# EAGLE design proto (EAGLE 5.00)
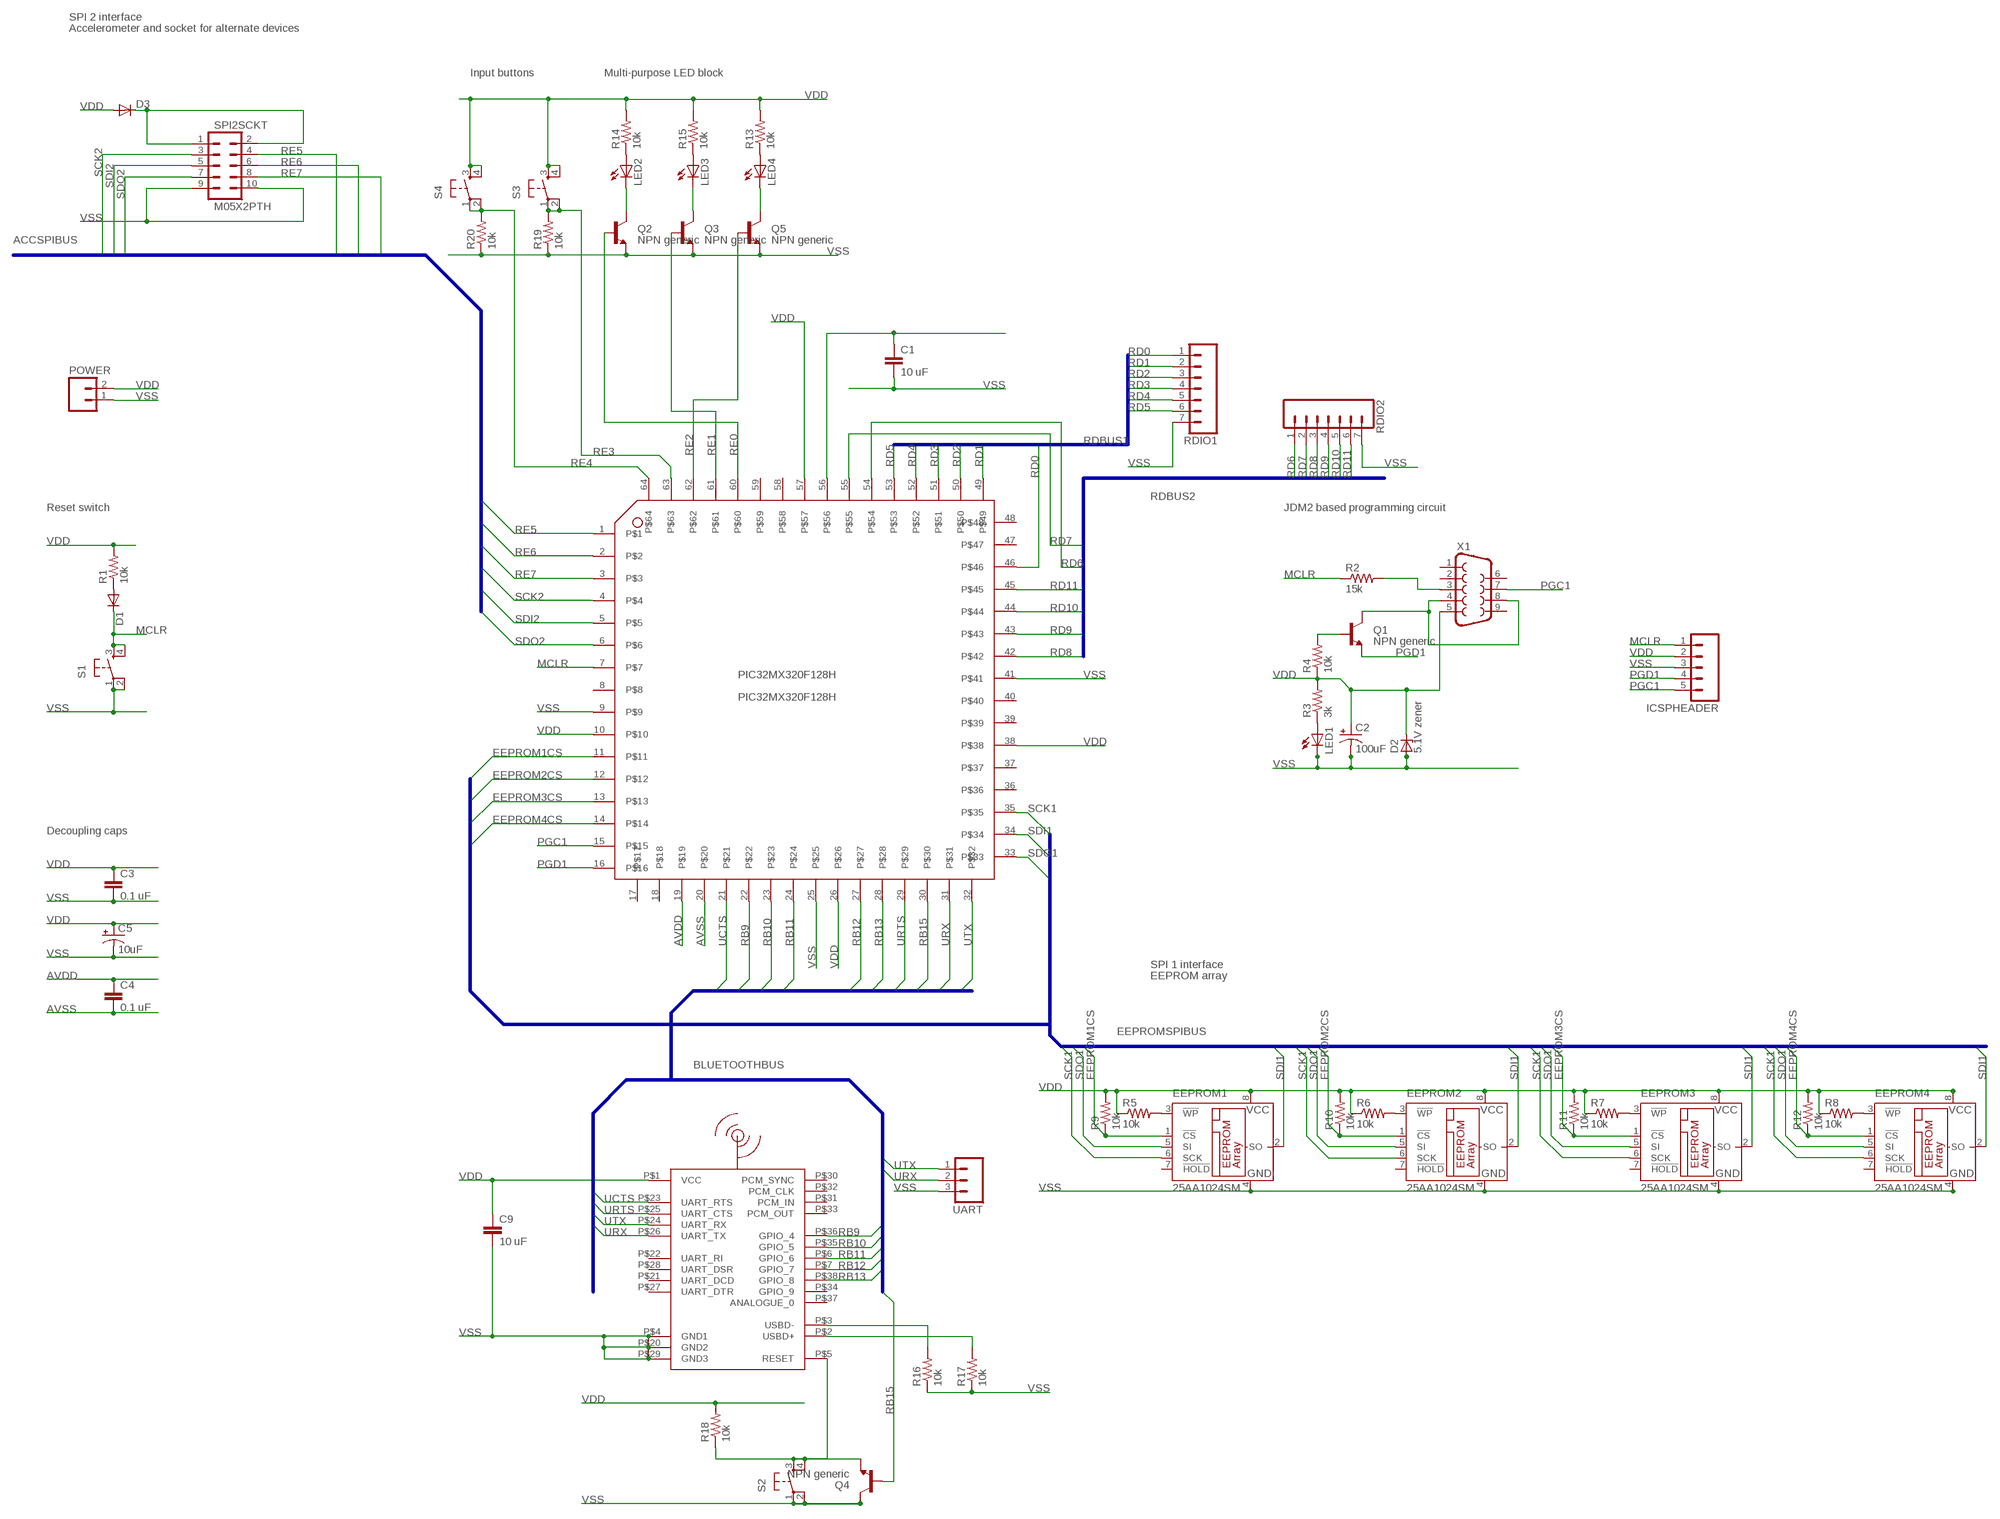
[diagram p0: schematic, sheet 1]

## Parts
C1  10 uF  CAP0603  [0603]
C2  100uF  CAP_POLPTH1  [CPOL-RADIAL-100UF-25V]
C3  0.1 uF  CAP0603  [0603]
C4  0.1 uF  CAP0603  [0603]
C5  10uF  CAP_POLPTH1  [CPOL-RADIAL-100UF-25V]
C9  10 uF  CAP0603  [0603]
D1  DIODESMA  [SMA-DIODE]
D2  5.1V zener  ZENER-DIODESMB  [SMB]
D3  DIODESMA  [SMA-DIODE]
EEPROM1  25AA1024SM  [SO-08M]
EEPROM2  25AA1024SM  [SO-08M]
EEPROM3  25AA1024SM  [SO-08M]
EEPROM4  25AA1024SM  [SO-08M]
ICSPHEADER  M05  [1X05]
LED1  LED1206  [LED-1206]
LED2  LED1206  [LED-1206]
LED3  LED1206  [LED-1206]
LED4  LED1206  [LED-1206]
PIC32MX320F128H  PIC32MX320F128H  [TQFP64]
POWER  M02PTH  [1X02]
Q1  NPN generic  TRANSISTOR_NPNSOT23  [SOT23]
Q2  NPN generic  TRANSISTOR_NPNSOT23  [SOT23]
Q3  NPN generic  TRANSISTOR_NPNSOT23  [SOT23]
Q4  NPN generic  TRANSISTOR_NPNSOT23  [SOT23]
Q5  NPN generic  TRANSISTOR_NPNSOT23  [SOT23]
R1  10k  RESISTOR0603  [0603]
R2  15k  RESISTOR0603  [0603]
R3  3k  RESISTOR0603  [0603]
R4  10k  RESISTOR0603  [0603]
R5  10k  RESISTOR0603  [0603]
R6  10k  RESISTOR0603  [0603]
R7  10k  RESISTOR0603  [0603]
R8  10k  RESISTOR0603  [0603]
R9  10k  RESISTOR0603  [0603]
R10  10k  RESISTOR0603  [0603]
R11  10k  RESISTOR0603  [0603]
R12  10k  RESISTOR0603  [0603]
R13  10k  RESISTOR0603  [0603]
R14  10k  RESISTOR0603  [0603]
R15  10k  RESISTOR0603  [0603]
R16  10k  RESISTOR0603  [0603]
R17  10k  RESISTOR0603  [0603]
R18  10k  RESISTOR0603  [0603]
R19  10k  RESISTOR0603  [0603]
R20  10k  RESISTOR0603  [0603]
RDIO1  M07  [1X07]
RDIO2  M07  [1X07]
S1  TAC_SWITCHSND  [TACTILE_SWITCH_SMD]
S2  TAC_SWITCHSND  [TACTILE_SWITCH_SMD]
S3  TAC_SWITCHSND  [TACTILE_SWITCH_SMD]
S4  TAC_SWITCHSND  [TACTILE_SWITCH_SMD]
SPI2SCKT  M05X2PTH  [AVR_ICSP]
U$2  BISMS02BI-01  [BISM]
UART  M03PTH  [1X03]
X1  DB9  [DB9]

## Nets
AVDD: C4.1 PIC32MX320F128H.19
AVSS: C4.2 PIC32MX320F128H.20
EEPROM1CS: EEPROM1.1(!CS) PIC32MX320F128H.11 R9.1
EEPROM2CS: EEPROM2.1(!CS) PIC32MX320F128H.12 R10.1
EEPROM3CS: EEPROM3.1(!CS) PIC32MX320F128H.13 R11.1
EEPROM4CS: EEPROM4.1(!CS) PIC32MX320F128H.14 R12.1
MCLR: D1.C ICSPHEADER.1 PIC32MX320F128H.7 R2.1 S1.3 S1.4
N$1: C1.1 PIC32MX320F128H.56
N$2: D1.A R1.1
N$3: R2.2 X1.3
N$4: Q1.3(C) X1.4 X1.8
N$5: LED1.A R3.1
N$6: Q1.1(B) R4.2
N$7: EEPROM4.3(!WP) R8.2
N$8: EEPROM3.3(!WP) R7.2
N$9: EEPROM2.3(!WP) R6.2
N$10: EEPROM1.3(!WP) R5.2
N$11: R16.2 U$2.P$3(USBD-)
N$12: LED4.A R13.1
N$13: LED4.C Q5.3(C)
N$15: D3.C SPI2SCKT.1 SPI2SCKT.2
N$16: LED2.A R14.1
N$17: LED3.A R15.1
N$18: LED2.C Q2.3(C)
N$19: LED3.C Q3.3(C)
N$20: R17.2 U$2.P$2(USBD+)
N$21: Q4.2(E) R18.1 S2.3 S2.4 U$2.P$5(RESET)
PGC1: ICSPHEADER.5 PIC32MX320F128H.15 X1.7
PGD1: ICSPHEADER.4 PIC32MX320F128H.16 Q1.2(E)
RB9: PIC32MX320F128H.22 U$2.P$36(GPIO_4)
RB10: PIC32MX320F128H.23 U$2.P$35(GPIO_5)
RB11: PIC32MX320F128H.24 U$2.P$6(GPIO_6)
RB12: PIC32MX320F128H.27 U$2.P$7(GPIO_7)
RB13: PIC32MX320F128H.28 U$2.P$38(GPIO_8)
RB15: PIC32MX320F128H.30 Q4.1(B)
RD0: PIC32MX320F128H.46 RDIO1.1
RD1: PIC32MX320F128H.49 RDIO1.2
RD2: PIC32MX320F128H.50 RDIO1.3
RD3: PIC32MX320F128H.51 RDIO1.4
RD4: PIC32MX320F128H.52 RDIO1.5
RD5: PIC32MX320F128H.53 RDIO1.6
RD6: PIC32MX320F128H.54 RDIO2.1
RD7: PIC32MX320F128H.55 RDIO2.2
RD8: PIC32MX320F128H.42 RDIO2.3
RD9: PIC32MX320F128H.43 RDIO2.4
RD10: PIC32MX320F128H.44 RDIO2.5
RD11: PIC32MX320F128H.45 RDIO2.6
RE0: PIC32MX320F128H.60 Q2.1(B)
RE1: PIC32MX320F128H.61 Q3.1(B)
RE2: PIC32MX320F128H.62 Q5.1(B)
RE3: PIC32MX320F128H.63 R19.2 S3.1 S3.2
RE4: PIC32MX320F128H.64 R20.2 S4.1 S4.2
RE5: PIC32MX320F128H.1 SPI2SCKT.4
RE6: PIC32MX320F128H.2 SPI2SCKT.6
RE7: PIC32MX320F128H.3 SPI2SCKT.8
SCK1: EEPROM1.6(SCK) EEPROM2.6(SCK) EEPROM3.6(SCK) EEPROM4.6(SCK) PIC32MX320F128H.35
SCK2: PIC32MX320F128H.4 SPI2SCKT.3
SDI1: EEPROM1.2(SO) EEPROM2.2(SO) EEPROM3.2(SO) EEPROM4.2(SO) PIC32MX320F128H.34
SDI2: PIC32MX320F128H.5 SPI2SCKT.5
SDO1: EEPROM1.5(SI) EEPROM2.5(SI) EEPROM3.5(SI) EEPROM4.5(SI) PIC32MX320F128H.33
SDO2: PIC32MX320F128H.6 SPI2SCKT.7
UCTS: PIC32MX320F128H.21 U$2.P$23(UART_RTS)
URTS: PIC32MX320F128H.29 U$2.P$25(UART_CTS)
URX: PIC32MX320F128H.31 U$2.P$26(UART_TX) UART.2
UTX: PIC32MX320F128H.32 U$2.P$24(UART_RX) UART.1
VDD: C2.1(+) C3.1 C5.1(+) C9.1 D2.C D3.A EEPROM1.8(VCC) EEPROM2.8(VCC) EEPROM3.8(VCC) EEPROM4.8(VCC) ICSPHEADER.2 PIC32MX320F128H.10 PIC32MX320F128H.26 PIC32MX320F128H.38 PIC32MX320F128H.57 POWER.2 R1.2 R3.2 R4.1 R5.1 R6.1 R7.1 R8.1 R9.2 R10.2 R11.2 R12.2 R13.2 R14.2 R15.2 R18.2 S3.3 S3.4 S4.3 S4.4 U$2.P$1(VCC) X1.5
VSS: C1.2 C2.2(-) C3.2 C5.2(-) C9.2 D2.A EEPROM1.4(GND) EEPROM2.4(GND) EEPROM3.4(GND) EEPROM4.4(GND) ICSPHEADER.3 LED1.C PIC32MX320F128H.9 PIC32MX320F128H.25 PIC32MX320F128H.41 POWER.1 Q2.2(E) Q3.2(E) Q4.3(C) Q5.2(E) R16.1 R17.1 R19.1 R20.1 RDIO1.7 RDIO2.7 S1.1 S1.2 S2.1 S2.2 SPI2SCKT.9 SPI2SCKT.10 U$2.P$4(GND1) U$2.P$20(GND2) U$2.P$29(GND3) UART.3
Unconnected: EEPROM1.7(!HOLD) EEPROM2.7(!HOLD) EEPROM3.7(!HOLD) EEPROM4.7(!HOLD) PIC32MX320F128H.8 PIC32MX320F128H.17 PIC32MX320F128H.18 PIC32MX320F128H.36 PIC32MX320F128H.37 PIC32MX320F128H.39 PIC32MX320F128H.40 PIC32MX320F128H.47 PIC32MX320F128H.48 PIC32MX320F128H.58 PIC32MX320F128H.59 U$2.P$21(UART_DCD) U$2.P$22(UART_RI) U$2.P$27(UART_DTR) U$2.P$28(UART_DSR) U$2.P$30(PCM_SYNC) U$2.P$31(PCM_IN) U$2.P$32(PCM_CLK) U$2.P$33(PCM_OUT) U$2.P$34(GPIO_9) U$2.P$37(ANALOGUE_0) X1.1 X1.2 X1.6 X1.9

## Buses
EEPROMSPIBUS
ACCSPIBUS
RDBUS1
RDBUS2
BLUETOOTHBUS

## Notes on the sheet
- SPI 2 interface
- Accelerometer and socket for alternate devices
- Input buttons | Multi-purpose LED block
- Reset switch | JDM2 based programming circuit
- Decoupling caps
- SPI 1 interface
- EEPROM array

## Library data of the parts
C1 C3 C4 C9 = SparkFun:CAP: Capacitor
C2 C5 = SparkFun:CAP_POL: Capacitor Polarized
D1 D3 = SparkFun:DIODE: Diode
D2 = diode:ZENER-DIODE: Z-Diode
EEPROM1-EEPROM4 = microchip:25*: Serial EEPROM SPI bus
ICSPHEADER = SparkFun:M05: Header 5 Standard 5-pin 0.1" header. Use with straight break away headers (SKU : PRT-00116), right angle break away headers (PRT-00553), swiss pins (PRT-00743), machine pins (PRT-00117), and female headers (PRT-00115). Molex polarized connector foot print use with SKU : PRT-08230 with associated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
LED1-LED4 = SparkFun:LED: LEDs
PIC32MX320F128H = microchip:PIC32MX320F128H: 64 pin general purpose 32bit PIC microcontroller Source: http://ww1.microchip.com/downloads/en/DeviceDoc/PIC32MX_Datasheet_v3_61143C.pdf
POWER = SparkFun:M02: Header 2
Q1-Q5 = SparkFun:TRANSISTOR_NPN: Transistor NPN BJT configuration in SOT23 package. MMBT2222 is the common NPN we use. Double check BCE configuration again layout.
R1-R20 = SparkFun:RESISTOR: Resistor
RDIO1 RDIO2 = SparkFun:M07: Header 7 Standard 7-pin 0.1" header. Use with straight break away headers (SKU : PRT-00116), right angle break away headers (PRT-00553), swiss pins (PRT-00743), machine pins (PRT-00117), and female headers (PRT-00115).
S1-S4 = SparkFun:TAC_SWITCH: Momentary Switch Button commonly used for reset or general input. Spark Fun Electronics SKU : COM-00097
SPI2SCKT = SparkFun:M05X2: Header 5x2 Standard 10-pin dual row 0.1" header. Commonly used with AVR-ISP. Use with Spark Fun Electronics SKU: PRT-00778
U$2 = errata:BISMS02BI-01: Ezurio BISM bluetooth module http://uk.rs-online.com/web/search/searchBrowseAction.html?method=getProduct&R=0188949 The Ezurio Embedded Bluetooth Module provides a robust and reliable Bluetooth connection along with a simple AT command based programming interface. The BISMII module is a Class 1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
UART = SparkFun:M03: Header 3 Standard 3-pin 0.1" header. Use with straight break away headers (SKU : PRT-00116), right angle break away headers (PRT-00553), swiss pins (PRT-00743), machine pins (PRT-00117), and female headers (PRT-00115). Molex polarized connector foot print use with SKU : PRT-08232 with associated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
X1 = SparkFun:DB9: DB9 Connector Standard DB9 (D-Sub 9) serial connector. Can be used for CAN bus as well as RS485 and RS232. Footprint production proven. Spark Fun Electronics SKU : PRT-00429

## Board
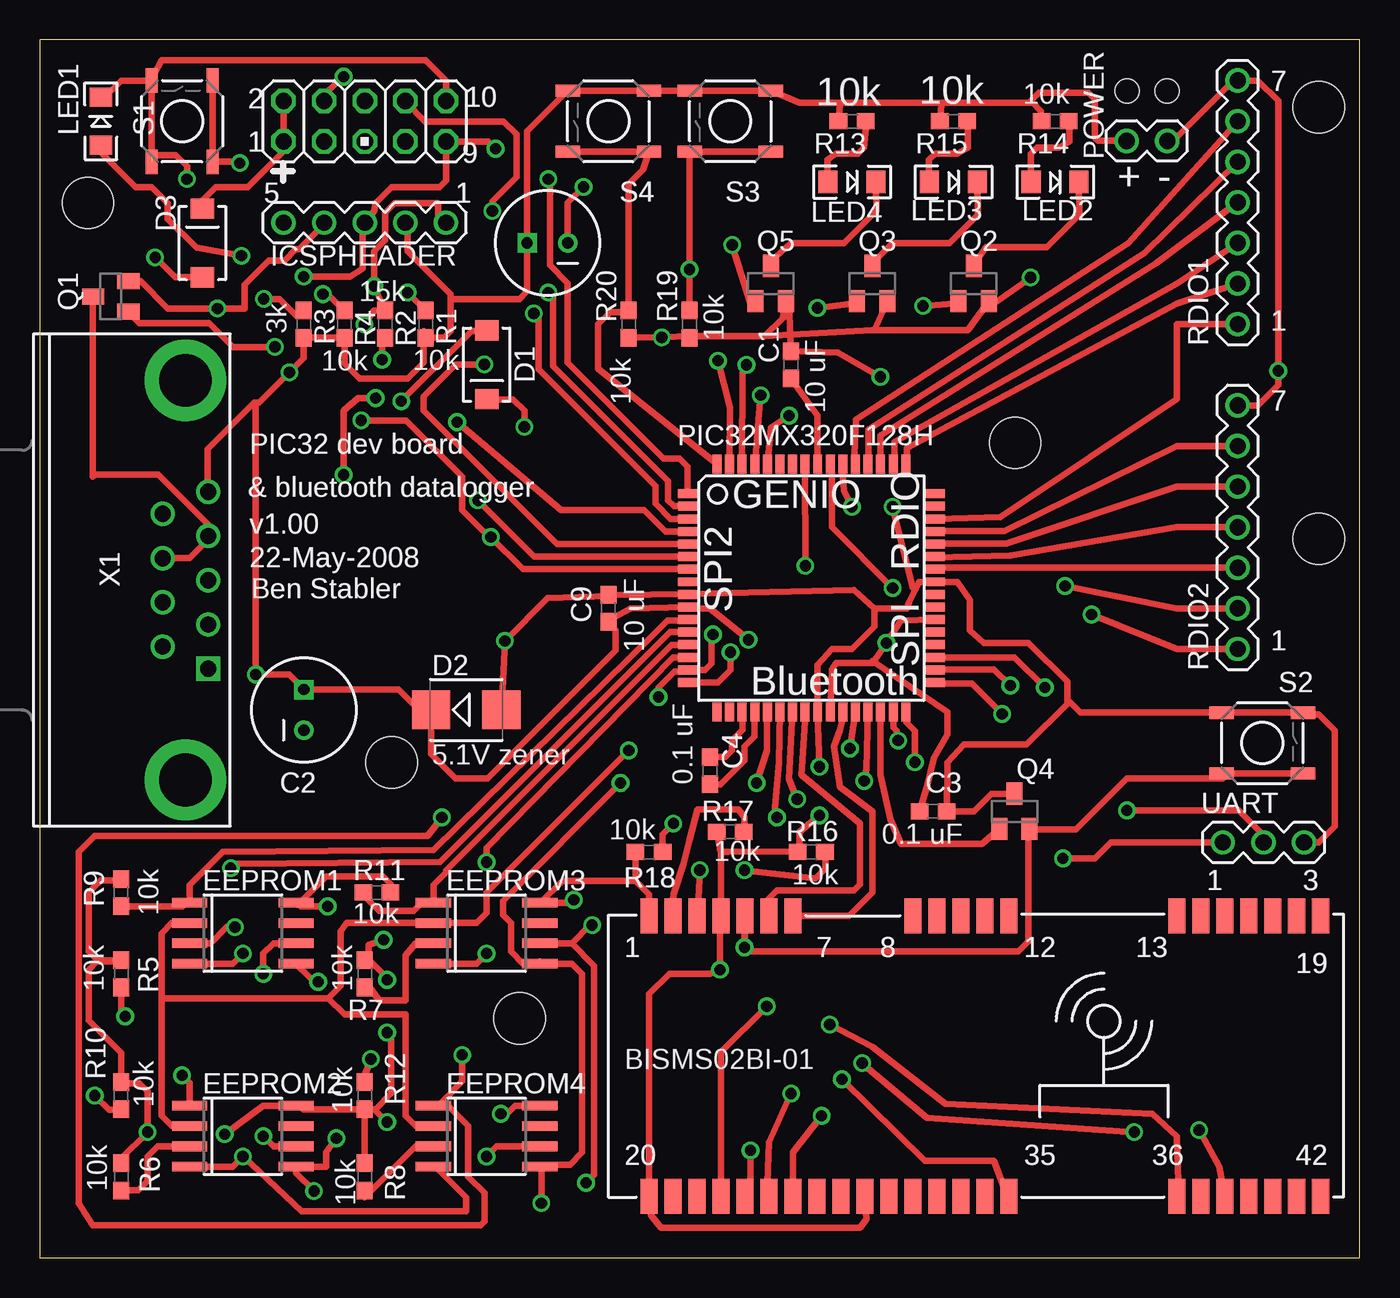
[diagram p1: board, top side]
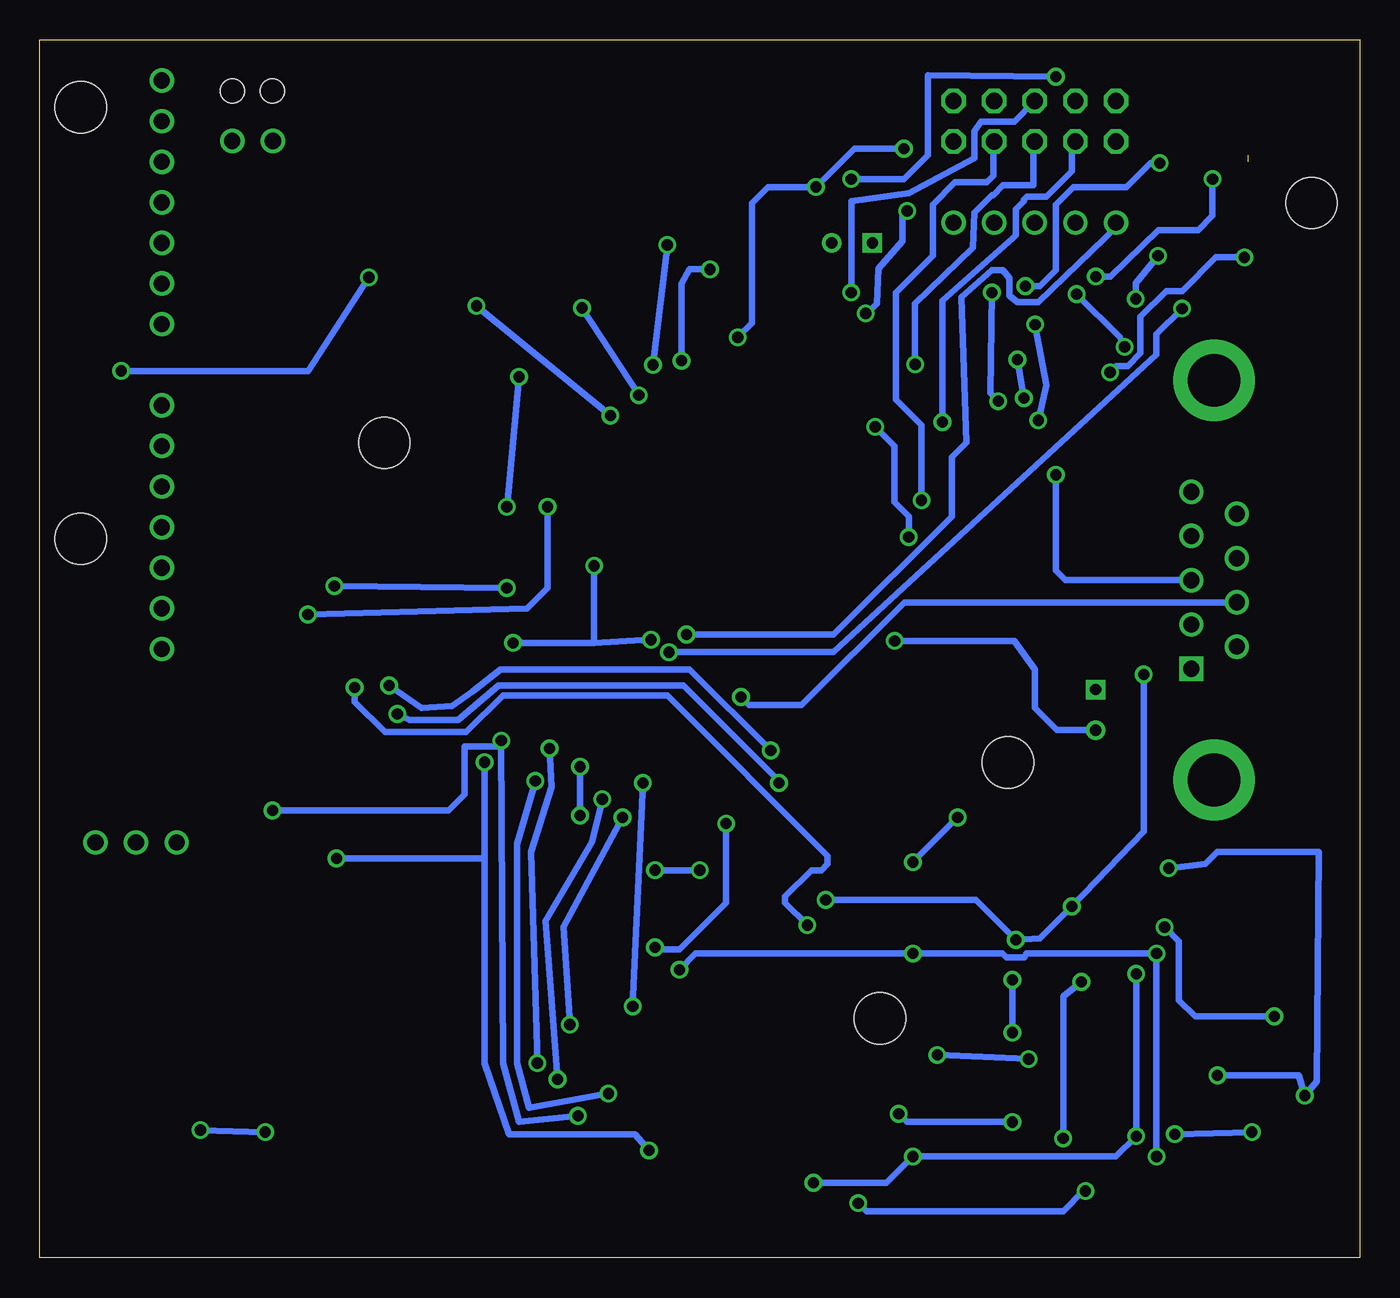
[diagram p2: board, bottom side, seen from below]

Size 82.55 x 76.2 mm. Coordinates in mm from the lower left corner, seen from the top.
Outline: 0,0 82.55,0 82.55,76.2 0,76.2 0,0
Copper layers (1*16): Top 0.035mm / dielectric 1.5mm / Bottom 0.035mm
Design rules "default": minimum track width 10mil, minimum drill 24mil, track to track 8mil, track to pad 8mil, pad to pad 8mil, via to via 8mil, smd to smd 8mil, copper to edge 40mil, drill to drill 8mil, minimum pad ring 10mil, minimum via ring 8mil, stop-mask expansion 4mil, vias tented up to drill 0mil, thermal gap 10mil
Holes 1.5 mm at 68,73 70.5,73
Holes 3.2 mm at 3,66 80,72 80,45 30,15 22,31 61,51

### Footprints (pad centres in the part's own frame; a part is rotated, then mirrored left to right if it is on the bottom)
0603 = smd 1.1 x 1: 1 -0.85,0; 2 0.85,0
CPOL-RADIAL-100UF-25V = drill 0.7 square: 1 1.27,0 | drill 0.7 round: 2 -1.27,0
SMA-DIODE = smd 1.27 x 1.47: A -2.15,0; C 2.15,0
SMB = smd 2.4 x 2.4: A 2.2,0; C -2.2,0
SO-08M = smd 0.6 x 2.2: 1 -1.905,-3.33; 2 -0.635,-3.33; 3 0.635,-3.33; 4 1.905,-3.33; 5 1.905,3.33; 6 0.635,3.33; 7 -0.635,3.33; 8 -1.905,3.33
1X05 = drill 1.016 round: 1 0,0; 2 2.54,0; 3 5.08,0; 4 7.62,0; 5 10.16,0
LED-1206 = smd 1.2 x 1.4: A -1.5,0; C 1.5,0
TQFP64 = smd 1.194 x 0.559: 1 -7.76,5.905; 2 -7.76,5.118; 3 -7.76,4.331; 4 -7.76,3.543; 5 -7.76,2.756; 6 -7.76,1.968; 7 -7.76,1.181; 8 -7.76,0.394; 9 -7.76,-0.394; 10 -7.76,-1.181; 11 -7.76,-1.968; 12 -7.76,-2.756; 13 -7.76,-3.543; 14 -7.76,-4.331; 15 -7.76,-5.118; 16 -7.76,-5.905; 33 7.76,-5.905; 34 7.76,-5.118; 35 7.76,-4.331; 36 7.76,-3.543; 37 7.76,-2.756; 38 7.76,-1.968; 39 7.76,-1.181; 40 7.76,-0.394; 41 7.76,0.394; 42 7.76,1.181; 43 7.76,1.968; 44 7.76,2.756; 45 7.76,3.543; 46 7.76,4.331; 47 7.76,5.118; 48 7.76,5.905 | smd 0.559 x 1.194: 17 -5.905,-7.76; 18 -5.118,-7.76; 19 -4.331,-7.76; 20 -3.543,-7.76; 21 -2.756,-7.76; 22 -1.968,-7.76; 23 -1.181,-7.76; 24 -0.394,-7.76; 25 0.394,-7.76; 26 1.181,-7.76; 27 1.968,-7.76; 28 2.756,-7.76; 29 3.543,-7.76; 30 4.331,-7.76; 31 5.118,-7.76; 32 5.905,-7.76; 49 5.905,7.76; 50 5.118,7.76; 51 4.331,7.76; 52 3.543,7.76; 53 2.756,7.76; 54 1.968,7.76; 55 1.181,7.76; 56 0.394,7.76; 57 -0.394,7.76; 58 -1.181,7.76; 59 -1.968,7.76; 60 -2.756,7.76; 61 -3.543,7.76; 62 -4.331,7.76; 63 -5.118,7.76; 64 -5.905,7.76
1X02 = drill 1.016 round: 1 0,0; 2 2.54,0
SOT23 = smd 1 x 1.4: 1 -0.95,-1.1; 2 0.95,-1.1; 3 0,1.1
1X07 = drill 1.016 round: 1 0,0; 2 2.54,0; 3 5.08,0; 4 7.62,0; 5 10.16,0; 6 12.7,0; 7 15.24,0
TACTILE_SWITCH_SMD = smd 1.524 x 0.762: 1 -2.54,1.905; 2 2.54,1.905; 3 -2.54,-1.905; 4 2.54,-1.905
AVR_ICSP = drill 1.016 octagon: 1 -1.27,5.08; 2 1.27,5.08; 3 -1.27,2.54; 4 1.27,2.54; 5 -1.27,0; 6 1.27,0; 7 -1.27,-2.54; 8 1.27,-2.54; 9 -1.27,-5.08; 10 1.27,-5.08
BISM = smd 1.067 x 2.184: P$1 2.55,17.6; P$2 4.05,17.6; P$3 5.55,17.6; P$4 7.05,17.6; P$5 8.55,17.6; P$6 10.05,17.6; P$7 11.55,17.6; P$8 19.05,17.6; P$9 20.55,17.6; P$10 22.05,17.6; P$11 23.55,17.6; P$12 25.05,17.6; P$13 35.55,17.6; P$14 37.05,17.6; P$15 38.55,17.6; P$16 40.05,17.6; P$17 41.55,17.6; P$18 43.05,17.6; P$19 44.55,17.6; P$20 2.55,0.05; P$21 4.05,0.05; P$22 5.55,0.05; P$23 7.05,0.05; P$24 8.55,0.05; P$25 10.05,0.05; P$26 11.55,0.05; P$27 13.05,0.05; P$28 14.55,0.05; P$29 16.05,0.05; P$30 17.55,0.05; P$31 19.05,0.05; P$32 20.55,0.05; P$33 22.05,0.05; P$34 23.55,0.05; P$35 25.05,0.05; P$36 35.55,0.05; P$37 37.05,0.05; P$38 38.55,0.05; P$39 40.05,0.05; P$40 41.55,0.05; P$41 43.05,0.05; P$42 44.55,0.05
1X03 = drill 1.016 round: 1 0,0; 2 2.54,0; 3 5.08,0
DB9 = drill 1.016 square: 1 -5.54,-1.42 | drill 1.016 round: 2 -2.77,-1.42; 3 0,-1.42; 4 2.77,-1.42; 5 5.54,-1.42; 6 -4.15,1.42; 7 -1.38,1.42; 8 1.38,1.42; 9 4.15,1.42 | drill 3.302 pad 5.08 round: G1 -12.5,0; G2 12.5,0

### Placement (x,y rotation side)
C1  46.99,55.88 90 top
C2  16.51,34.29 90 top
C3  55.88,27.94 0 top
C4  41.91,30.48 270 top
C5  31.75,63.5 180 top
C9  35.56,40.64 90 top
D1  27.94,55.88 270 top
D2  26.67,34.29 0 top
D3  10.16,63.5 90 top
EEPROM1  12.7,20.32 270 top
EEPROM2  12.7,7.62 270 top
EEPROM3  27.94,20.32 270 top
EEPROM4  27.94,7.62 270 top
ICSPHEADER  25.4,64.77 180 top
LED1  3.81,71.12 90 top
LED2  63.5,67.31 0 top
LED3  57.15,67.31 0 top
LED4  50.8,67.31 0 top
PIC32MX320F128H  48.26,41.91 0 top
POWER  70.52,69.89 180 top
Q1  4.43,60.15 90 top
Q2  58.42,60.96 0 top
Q3  52.07,60.96 0 top
Q4  60.96,27.94 0 top
Q5  45.72,60.96 0 top
R1  24.13,58.42 270 top
R2  21.59,58.42 270 top
R3  16.51,58.42 270 top
R4  19.05,58.42 90 top
R5  5.08,17.78 270 top
R6  5.08,5.08 270 top
R7  20.32,17.78 270 top
R8  20.32,5.08 270 top
R9  5.08,22.86 90 top
R10  5.08,10.16 90 top
R11  21.08,22.86 0 top
R12  20.32,10.16 270 top
R13  50.8,71.12 180 top
R14  63.5,71.12 180 top
R15  57.15,71.12 180 top
R16  48.26,25.4 0 top
R17  43.18,26.67 0 top
R18  38.1,25.4 180 top
R19  40.64,58.42 90 top
R20  36.83,58.42 90 top
RDIO1  74.93,58.42 90 top
RDIO2  74.93,38.1 90 top
S1  8.89,71.12 90 top
S2  76.47,32.21 0 top
S3  43.18,71.12 180 top
S4  35.56,71.12 180 top
SPI2SCKT  20.32,71.12 90 top
U$2  35.56,3.81 0 top
UART  74,26 0 top
X1  9.1,42.4 90 top

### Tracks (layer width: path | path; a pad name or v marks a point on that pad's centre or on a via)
AVDD
  Top 0.406: C4.1 42.89,31.33 43.31,31.75 43.31,32.38 43.94,33.02 43.94,34.16 PIC32MX320F128H.19
AVSS
  Top 0.406: C4.2 42.58,29.63 44.07,31.11 44.07,32 44.7,32.64 44.7,33.91 44.72,33.92 PIC32MX320F128H.20
EEPROM1CS
  Top 0.406: PIC32MX320F128H.11 40.5,39.89 40.51,39.88 39.24,39.88 38.35,38.99 24.64,25.53 11.43,25.4 9.37,23.34 EEPROM1.1 9.14,22.23 8.93,22.01 R9.1
EEPROM2CS  (via drill 0.7)
  Top 0.406: EEPROM2.1 9.37,10.95 v8.89,11.43 | v3.43,10.16 4.32,9.27 5.08,9.27 | 5.08,9.27 R10.1 | 5.08,9.27 5.21,9.14 | PIC32MX320F128H.12 39.41,39.15 25.02,24.77 12.19,24.64 v11.94,24.38
  Bottom 0.406: v8.89,11.43 3.81,11.43 v3.43,10.16 2.67,11.05 2.54,25.4 8.89,25.4 9.65,24.64 v11.94,24.38
EEPROM3CS
  Top 0.406: R11.1 20.23,22.77 20.19,22.73 21.21,21.72 23.37,21.72 23.88,22.23 EEPROM3.1 24.61,23.34 25.4,24.13 25.4,24.26 39.5,38.35 40.51,38.35 PIC32MX320F128H.13
EEPROM4CS  (via drill 0.7)
  Top 0.406: R12.1 20.32,11.43 v20.7,12.45 | EEPROM4.1 24.89,9.53 25.21,9.84 | v26.42,12.7 26.42,11.05 25.21,9.84 | PIC32MX320F128H.14 39.61,37.58 27.94,25.65 v27.94,24.77 | v25.15,27.56 24.26,26.42 3.43,26.42 2.41,25.4 2.41,3.43 3.3,2.03 27.56,2.03 27.81,2.29 27.81,4.06 26.8,5.08 26.8,8.26 25.21,9.84
  Bottom 0.406: v26.42,12.7 v20.7,12.45 | v25.15,27.56 v27.94,24.77
MCLR  (via drill 0.7)
  Top 0.406: 10.79,73.79 S1.4 S1.3 12.42,68.58 v12.5,68.5 | v20.89,60.8 R2.1 20.87,59.27 v20.3,58.4 | v20.89,60.8 20.9,63 21.59,63.69 21.59,65.39 22.2,66 24.9,66 24.9,65.3 25.4,64.8 ICSPHEADER.1 | v20.89,60.8 20.8,60.8 | v20.89,60.8 v20.9,60.8 | PIC32MX320F128H.7 30.21,43.09 v28.2,45.1 28.2,45 26.4,46.8 26.4,48.9 22.9,52.4 v20.1,52.4 | v30.3,52 30.3,53 29.6,53.7 27.9,53.7 27.87,53.73 | 27.87,53.73 27.8,53.8 | 27.87,53.73 D1.C
  Bottom 0.406: v12.5,68.5 13.1,68.5 14.6,67 17.9,67 19,65.9 19,61.8 20,60.8 v20.9,60.8 | v28.2,45.1 28.2,46.4 29.1,47.3 29.1,50.8 v30.3,52 | v20.3,58.4 19.6,54.6 v20.1,52.4
N$1
  Top 0.406: C1.1 48.64,52.7 48.64,49.4 PIC32MX320F128H.56
N$2  (via drill 0.7)
  Top 0.406: v23,60.4 R1.1 | v22.6,53.6 27,58 27.9,58 D1.A
  Bottom 0.406: v23,60.4 23.1,54.1 v22.6,53.6
N$3  (via drill 0.7)
  Top 0.406: v19,49 19,53 19.9,53.8 v21,53.8 | R2.2 21.63,57.57 21.7,57.5 21.4,57.2 v21.4,56.2
  Bottom 0.406: X1.3 18.4,42.4 19,43 v19,49 | v21,53.8 v21.4,56.2
N$4
  Top 0.406: X1.8 9.38,43.78 10.6,45 10.52,45.08 X1.4 10.52,45.88 7.4,49 3.4,49 3.3,48.9 3.3,60.1 3.35,60.15 | 3.35,60.15 3.4,60.2 | 3.35,60.15 Q1.3
N$5  (via drill 0.7)
  Top 0.406: LED1.A 3.81,69.19 6,67 7,67 8,66 8,65 9.8,63.2 v12.6,62.7 | v14,60 15,60 16,59 16.3,59 16.57,59.27 | 16.57,59.27 16.6,59.3 | 16.57,59.27 R3.1
  Bottom 0.406: v12.6,62.7 14,61 v14,60
N$6  (via drill 0.7)
  Top 0.406: 19.05,59.25 19.1,59.2 | 19.05,59.25 R4.2 | v17.7,60.3 18,60.3 19.05,59.25 | v14.7,57 12.1,57 10.6,58.5 6.2,58.5 5.53,59.17 Q1.1
  Bottom 0.406: v14.7,57 15,57.6 v17.7,60.3
N$7
  Top 0.406: EEPROM4.3 23.5,6.99 20.32,3.81 R8.2
N$8
  Top 0.406: EEPROM3.3 23.5,19.68 22.86,18.92 22.86,16.13 21.21,16.13 20.57,17.02 20.49,16.93 R7.2
N$9
  Top 0.406: R6.2 6.13,4.23 6.73,4.83 6.73,6.35 7.37,6.99 EEPROM2.3
N$10  (via drill 0.7)
  Top 0.406: R5.2 5.08,15.37 v5.33,15.11 | v12.19,20.7 11.68,20.7 10.67,19.68 EEPROM1.3 9.27,19.68
  Bottom 0.406: v5.33,15.11 10.29,15.11 11.3,16.13 11.3,19.81 v12.19,20.7
N$11  (via drill 0.7)
  Top 0.406: R16.2 49.15,24.38 48.51,23.75 v44.07,24.26 | U$2.P$3 41.15,21.34 v41.27,24.26
  Bottom 0.406: v41.27,24.26 v44.07,24.26
N$12
  Top 0.406: LED4.A 49.28,68.71 49.78,69.09 51.18,69.09 51.56,69.47 51.69,70.99 R13.1
N$13
  Top 0.406: LED4.C 52.32,65.53 50.29,63.5 46.99,63.5 45.72,62.36 Q5.3
N$15
  Top 0.406: SPI2SCKT.2 SPI2SCKT.1 15.24,69.24 13,67 11,67 10,66 10.16,65.84 D3.C
N$16
  Top 0.406: LED2.A 61.98,69.09 62.36,69.47 63.75,69.47 64.39,69.85 64.39,70.87 R14.1
N$17
  Top 0.406: LED3.A 55.63,68.71 56.01,69.09 57.4,69.09 58.04,69.47 58.04,71.12 R15.1
N$18
  Top 0.406: LED2.C 65.02,65.28 62.99,63.25 59.18,63.25 58.42,62.1 Q2.3
N$19
  Top 0.406: LED3.C 58.67,65.28 56.9,63.5 53.34,63.5 51.94,62.1 Q3.3
N$20
  Top 0.406: R17.2 44.07,27.56 43.69,28.07 41.15,28.07 40.64,26.16 40.26,24.64 39.62,22.73 39.5,21.46 U$2.P$2
N$21  (via drill 0.7)
  Top 0.406: 44.11,20.83 U$2.P$5 | 44.11,20.83 44.11,19.26 44.2,19.18 61.21,19.18 61.85,19.81 61.85,26.67 61.98,26.8 | 61.98,26.8 61.93,26.84 Q4.2 | R18.1 38.95,26.5 v39.62,27.18 | 44.11,20.83 44.07,20.83 v44.07,19.43 | S2.4 S2.3 73.93,30.07 74,30 68,30 64.8,26.8 61.98,26.8
  Bottom 0.406: v39.62,27.18 39.62,22.23 42.55,19.3 43.94,19.3 v44.07,19.43
PGC1  (via drill 0.7)
  Top 0.406: v42.1,39 42,38.9 42,37.2 41.59,36.79 PIC32MX320F128H.15 40.6,36.7 39.7,36.7 38.7,35.7 v38.7,35.1
  Bottom 0.406: v42.1,39 32.9,39 25.5,46.4 25.5,50.1 24.6,51 24.9,60.1 23,61.8 22.3,61.8 21.9,61.3 21.9,60.2 21.4,59.8 20.1,59.8 15.1,64.6 15.24,64.74 ICSPHEADER.5 | X1.7 28.48,41.02 34.9,34.6 38.2,34.6 v38.7,35.1
PGD1  (via drill 0.7)
  Top 0.406: PIC32MX320F128H.16 42.4,36.01 43.2,36.8 v43.2,37.9 | ICSPHEADER.4 17.78,64.72 17.8,64.7 16.2,63.1 16,63.1 15.3,62.4 14.3,62.4 12.8,60.9 12.8,59.4 v11.1,59.4 8,59.4 6.3,61.1 Q1.2
  Bottom 0.406: v43.2,37.9 32.9,37.9 12.7,56.5 12.7,57.8 v11.1,59.4
RB9  (via drill 0.7)
  Top 0.406: PIC32MX320F128H.22 46.23,30.99 45.97,28.19 v46.1,27.56 | v49.4,14.61 52.07,13.21 56.64,9.65 69.6,9.02 71.12,7.62 71.25,3.81 U$2.P$36
  Bottom 0.406: v46.1,27.56 49.78,20.7 v49.4,14.61
RB10  (via drill 0.7)
  Top 0.406: PIC32MX320F128H.23 46.86,29.97 v47.37,28.7 | v50.16,11.18 55.37,6.1 59.69,6.1 60.58,3.68 U$2.P$35
  Bottom 0.406: v47.37,28.7 48.01,26.04 50.93,21.08 v50.16,11.18
RB11
  Top 0.406: U$2.P$6 45.61,22.5 46.1,22.99 50.93,22.99 51.31,23.37 51.31,27.18 47.62,30.23 47.88,34.04 PIC32MX320F128H.24
RB12
  Top 0.406: U$2.P$7 50.62,21.41 52.07,22.86 52.07,27.94 50.04,29.46 49.66,32 50.04,33.02 50.29,34.04 50.18,34.15 | 50.18,34.15 50.16,34.16 | 50.18,34.15 PIC32MX320F128H.27
RB13  (via drill 0.7)
  Top 0.406: v50.67,31.88 PIC32MX320F128H.28 | v51.44,12.19 55.5,8.76 v68.45,7.87 | v72.52,8 73.79,5.71 74.17,3.68 U$2.P$38
  Bottom 0.406: v50.67,31.88 50.55,29.46 51.82,25.4 v51.44,12.19 | v68.45,7.87 v72.52,8
RB15
  Top 0.406: Q4.1 58.93,25.91 53.85,25.91 53.21,27.43 52.58,30.23 52.58,33.91 PIC32MX320F128H.30
RD0
  Top 0.406: PIC32MX320F128H.46 60.07,46.35 71.12,53.72 71.12,58.42 RDIO1.1
RD1
  Top 0.406: RDIO1.2 71.12,59.69 54.23,50.67 54.23,49.53 PIC32MX320F128H.49
RD2
  Top 0.406: RDIO1.3 71.12,60.96 53.47,51.05 53.47,49.91 PIC32MX320F128H.50
RD3
  Top 0.406: RDIO1.4 69.85,62.23 52.58,51.44 52.58,49.66 PIC32MX320F128H.51
RD4
  Top 0.406: RDIO1.5 69.09,62.87 51.82,51.82 51.82,49.53 PIC32MX320F128H.52
RD5
  Top 0.406: RDIO1.6 68.07,63.5 51.05,52.45 50.93,49.53 PIC32MX320F128H.53
RD6  (via drill 0.7)
  Top 0.406: RDIO2.1 71.12,38.1 v65.79,40.26 | v50.8,46.99 50.29,48.01 50.16,49.53 PIC32MX320F128H.54
  Bottom 0.406: v65.79,40.26 52.07,40.64 50.8,41.91 v50.8,46.99
RD7  (via drill 0.7)
  Top 0.406: RDIO2.2 71.12,40.64 v64.14,42.04 | v53.34,41.91 49.53,45.72 49.53,49.53 PIC32MX320F128H.55
  Bottom 0.406: v53.34,41.91 v64.14,42.04
RD8
  Top 0.406: PIC32MX320F128H.42 55.97,43.09 55.88,43.18 RDIO2.3
RD9
  Top 0.406: RDIO2.4 71.12,45.72 60.71,43.94 55.88,43.81 PIC32MX320F128H.43
RD10
  Top 0.406: RDIO2.5 71.12,48.26 60.45,44.7 56.01,44.7 PIC32MX320F128H.44
RD11
  Top 0.406: RDIO2.6 71.12,50.8 60.33,45.47 55.88,45.47 PIC32MX320F128H.45
RE0  (via drill 0.7)
  Top 0.406: PIC32MX320F128H.60 45.72,51.94 v46.86,52.7 | Q2.1 57.15,59.69 v55.24,59.56
  Bottom 0.406: v46.86,52.7 v55.24,59.56
RE1  (via drill 0.7)
  Top 0.406: PIC32MX320F128H.61 v45.09,53.98 | Q3.1 50.8,59.69 v48.64,59.44
  Bottom 0.406: v45.09,53.98 v48.64,59.44
RE2  (via drill 0.7)
  Top 0.406: PIC32MX320F128H.62 43.94,55.37 v44.2,55.88 | Q5.1 44.45,59.69 v43.31,63.37
  Bottom 0.406: v44.2,55.88 v43.31,63.37
RE3  (via drill 0.7)
  Top 0.406: S3.2 40.51,69.22 | S3.2 S3.1 | 40.64,59.18 R19.2 v40.64,61.85 S3.2 | PIC32MX320F128H.63 43.18,53.21 v42.42,56.13
  Bottom 0.406: v42.42,56.13 42.42,60.96 41.91,61.85 v40.64,61.85
RE4
  Top 0.406: S4.2 S4.1 37.72,68.07 36.83,67.18 R20.2 36.7,59.18 35.69,59.18 34.92,58.42 34.92,55.63 PIC32MX320F128H.64
RE5  (via drill 0.7)
  Top 0.406: PIC32MX320F128H.1 40.5,49.5 40,50 39,50 33,56 33,61 31.9,62.1 31.9,67.4 v31.8,67.5 | v19,73.9 18,73 17.8,72.3 17.78,72.22 SPI2SCKT.4
  Bottom 0.406: v31.8,67.5 28.5,67.5 27,69 27,74 v19,73.9
RE6  (via drill 0.7)
  Top 0.406: PIC32MX320F128H.2 39.67,47.03 39.3,47.4 39.3,48.6 32.1,55.8 32.1,60.1 v31.8,60.4
  Bottom 0.406: v31.8,60.4 31.8,66.1 28.2,66.6 24.1,68.8 24.1,70.5 23.7,71.1 21.6,71.1 SPI2SCKT.6 | SPI2SCKT.6 20.3,72.4 | SPI2SCKT.6
RE7  (via drill 0.7)
  Top 0.406: PIC32MX320F128H.3 39.46,46.24 38.5,47.2 38.5,48.3 31.2,55.6 31.2,58.8 v30.9,59.1 | v28.3,65.5 28.3,66.1 29.8,67.6 29.8,70.3 29,71.1 24.1,71.1 22.86,72.34 SPI2SCKT.8
  Bottom 0.406: v30.9,59.1 30.8,59.1 30.2,59.7 30.1,61.9 28.6,63.6 28.6,65.2 v28.3,65.5
SCK1  (via drill 0.7)
  Top 0.406: EEPROM2.6 14.61,6.99 v13.97,7.62 | v13.97,17.78 13.97,19.05 14.61,19.68 EEPROM1.6 16.13,19.68 | 33.27,19.68 EEPROM3.6 | 33.27,19.68 34.67,18.29 34.67,5.21 v34.16,4.7 | EEPROM4.6 28.57,6.99 v27.94,6.35 | PIC32MX320F128H.35 60.97,37.58 v62.87,35.69 | v34.54,20.83 34.42,20.83 33.27,19.68
  Bottom 0.406: v13.97,17.78 v13.97,7.62 15.24,6.35 v27.94,6.35 29.59,4.7 v34.16,4.7 | v62.87,35.69 62.87,34.8 60.96,32.89 55.88,32.89 53.59,35.18 43.31,35.18 33.27,25.15 33.27,24.64 33.66,24.26 34.29,24.26 35.94,22.61 35.94,22.23 v34.54,20.83
SCK2  (via drill 0.7)
  Top 0.406: PIC32MX320F128H.4 39.15,45.45 37.8,46.8 32.6,46.8 v26.1,52.3
  Bottom 0.406: v26.1,52.3 26.1,59.9 21.7,63.8 21.5,64 21.5,65.6 21,66.1 21,66.2 20.8,66.4 19.6,66.4 18,68 18,70 17.85,69.85 SPI2SCKT.3
SDI1  (via drill 0.7)
  Top 0.406: EEPROM1.2 8.26,20.95 7.62,20.32 7.62,16.26 | 7.62,16.26 7.62,8.89 8.26,8.26 EEPROM2.2 9.4,8.26 | 18.03,16.26 18.8,17.02 18.8,20.45 19.18,20.95 EEPROM3.2 27.3,20.95 27.94,21.59 27.94,22.86 v36.83,31.75 | 7.62,16.26 18.03,16.26 | EEPROM4.2 23.5,8.26 22.86,8.89 22.86,15.24 19.05,15.24 18.03,16.26 | v60.71,35.81 59.69,36.83 56.01,36.83 PIC32MX320F128H.34
  Bottom 0.406: v36.83,31.75 41.91,36.83 53.72,36.83 55.5,35.43 56.77,34.54 58.67,34.42 v60.71,35.81
SDI2  (via drill 0.7)
  Top 0.406: PIC32MX320F128H.5 32.33,44.67 24,53 24,53.9 26,55.9 v27.8,55.9
  Bottom 0.406: v27.8,55.9 27.8,59.7 24.2,63.2 24.1,65.4 23,66.5 22.9,66.5 22.3,67.1 20.4,67.1 20.4,69.6 20.15,69.85 | 20.15,69.85 20,70 | 20.15,69.85 SPI2SCKT.5
SDO1  (via drill 0.7)
  Top 0.406: v17.14,4.19 16.03,5.31 EEPROM2.5 17.91,5.71 17.91,6.6 v18.54,7.49 | 31.27,5.81 31.24,5.84 33.15,5.84 33.91,6.6 33.91,17.78 33.27,18.41 31.37,18.41 31.27,18.51 | 31.27,5.81 EEPROM4.5 | v31.37,3.43 31.37,5.71 31.27,5.81 | 31.27,18.51 31.24,18.54 | 31.27,18.51 EEPROM3.5 30.23,18.41 29.46,19.18 29.46,20.95 28.96,21.46 28.96,22.35 v36.32,29.72 | v60.2,34.04 58.29,35.94 56.13,35.94 56.07,36.01 PIC32MX320F128H.33 | EEPROM1.5 16,18.41 16.89,17.53 v17.4,17.27
  Bottom 0.406: v17.14,4.19 17.27,4.19 18.54,2.92 30.86,2.92 v31.37,3.43 | v36.32,29.72 36.32,29.84 42.29,35.81 53.85,35.81 56.39,33.66 59.44,33.66 v60.2,34.04 | v18.54,7.49 18.54,16.38 v17.4,17.27
SDO2  (via drill 0.7)
  Top 0.406: PIC32MX320F128H.6 30.92,43.88 v27.4,47.4
  Bottom 0.406: v27.4,47.4 27.4,52.1 29,53.7 29,60.4 26.7,62.7 26.7,65.9 25.3,67.3 23.3,67.3 22.9,67.7 22.9,69.8 SPI2SCKT.7
UCTS  (via drill 0.7)
  Top 0.406: U$2.P$23 42.61,12.89 v45.47,15.75 | PIC32MX320F128H.21 45.5,34.07 45.47,34.04 45.47,31.75 v44.83,29.72
  Bottom 0.406: v45.47,15.75 v44.83,29.72
URTS  (via drill 0.7)
  Top 0.406: PIC32MX320F128H.29 51.69,30.61 v51.56,29.84 | v46.99,10.29 45.59,7.24 45.47,3.94 U$2.P$25
  Bottom 0.406: v51.56,29.84 52.7,25.91 52.7,12.19 51.94,9.4 v46.99,10.29
URX  (via drill 0.7)
  Top 0.406: v53.69,32.37 53.59,33.01 53.4,33.2 PIC32MX320F128H.31 | v48.9,8.89 47.12,6.6 47.12,3.56 U$2.P$26 | UART.2 76.54,26.46 75,28 v68,28
  Bottom 0.406: v48.9,8.89 52.58,8.51 53.59,12.19 v53.69,32.37 53.69,32.31 54,32 56,32 56,29 57,28 v68,28
UTX  (via drill 0.7)
  Top 0.406: v54.74,31.01 54.74,32.96 54.2,33.5 PIC32MX320F128H.32 | U$2.P$24 44.45,3.81 v44.45,6.73 | UART.1 67,26 66,25 v64,25
  Bottom 0.406: 54.74,25 54.74,12.19 53.21,7.75 45.34,7.75 v44.45,6.73 | 54.74,25 v54.74,31.01 | 54.74,25 v64,25
VDD  (via drill 0.7)
  Top 0.406: R12.2 R8.1 | R12.2 16.47,9.31 16.26,9.53 EEPROM2.8 13.97,9.53 v11.56,7.75 | R12.2 20.92,9.31 | 20.92,9.31 v21.72,8.51 | v28.83,9.02 29.21,9.02 29.72,9.53 EEPROM4.8 | 3.56,18.54 3.05,18.03 3.05,14.86 5.08,12.83 R10.2 5.08,10.92 6.22,10.92 6.73,10.41 v6.73,7.87 5.08,6.22 R6.1 | 3.68,18.54 5.21,18.54 5.12,18.63 R5.1 3.64,18.63 3.56,18.54 | 3.56,18.54 3.68,18.54 | 3.68,18.54 3.05,19.18 3.05,22.86 3.81,23.62 5.08,23.62 R9.2 | R11.2 21.93,23.41 21.46,23.88 17.91,23.88 16.13,22.1 16.03,22.2 EEPROM1.8 16.07,22.23 16.3,22 v18,22 | 37.25,23.58 R18.2 | 37.25,23.58 38.1,22.73 38.1,21.34 38.11,21.35 U$2.P$1 | 20.92,9.31 20.99,9.31 21.97,10.29 21.97,13.84 v21.72,14.1 | 20.57,18.67 20.54,18.63 R7.1 | v21.72,17.4 21.72,17.53 20.57,18.67 | R14.2 62.61,71.75 62.1,72.26 61.9,72.26 | 50.04,72.26 47.5,72.26 S3.3 S3.4 S4.3 | 50.04,72.26 56.39,72.26 | 56.39,72.26 61.9,72.26 | 56.39,72.26 56.39,72.14 R15.2 | 50.04,72.26 50.04,72.14 R13.2 | S4.3 37.72,73.03 | S4.4 32.89,73.03 | S4.4 S4.3 | PIC32MX320F128H.38 53.85,39.88 v52.96,38.48 52.13,37.3 | v44.32,38.68 41.91,40.64 40.64,40.64 PIC32MX320F128H.10 36.96,40.64 35.56,39.88 C9.1 35.51,39.79 | PIC32MX320F128H.26 49.53,36.83 49.78,37.21 52.07,37.21 52.13,37.3 | v47.88,43.31 PIC32MX320F128H.57 | C3.1 55.5,29.46 55.93,31.3 56.77,32.77 56.77,34.16 52.07,37.34 52.13,37.3 | EEPROM3.8 31.3,22.2 32.68,23.58 37.25,23.58 | EEPROM3.8 | 20.57,18.67 20.57,19.57 v21.5,19.9 | EEPROM3.8 33.23,22.23 v33.4,22.4 | 35.51,39.79 35.5,39.8 | 35.51,39.79 36,39.3 36,38 28,30 26,30 24.47,31.53 D2.C 24.47,34.23 24.5,34.2 24.3,34 24,34 22.44,35.56 C2.1 16.51,35.59 15.6,36.5 v13.5,36.5 13.5,53.5
  Top 0.406: S4.4 30.48,70.48 C5.1 30.48,60.48 30,60 25.7,60 | 19.05,57.55 19.1,57.5 | 19.05,57.55 R4.1 19.05,56.05 19,56 20,55 23,55 24,56 24,58 24.13,57.87 R1.2 25.27,57.57 25.7,58 25.7,60 | 19.05,57.55 19.03,57.57 R3.2 16.53,57.57 16.6,57.5 16.5,57.4 16.5,56.3 15.65,55.45 | 25.7,60 25.7,60.3 23,63 23,65 22.86,64.86 ICSPHEADER.2 | POWER.2 66.21,69.89 66,70.1 66,72.5 65.6,72.9 62.5,72.9 61.9,72.3 61.9,72.26 | 13.5,53.5 13.7,53.5 v15.6,55.4 | v15.6,55.4 15.65,55.45 | 13.5,53.5 13.4,53.5 10.5,50.6 10.5,48 10.44,47.94 | 10.44,47.94 10.4,47.9 | 10.44,47.94 X1.5 | D3.A 8.45,61.35 v7.2,62.6 | 15.65,55.45 15.7,55.4 v15.6,55.4
  Bottom 0.406: v21.72,8.51 28.32,8.51 v28.83,9.02 | v6.73,7.87 v11.56,7.75 | v21.72,14.1 v21.72,17.4 | v44.32,38.68 47.88,38.48 | 47.88,38.48 v52.96,38.48 | 47.88,38.48 v47.88,43.31 | v33.4,22.4 24,22.4 v21.5,19.9 20,20 v18,22 13.5,26.7 v13.5,36.5 | v7.2,62.6 9,62.6 11.1,60.5 12.1,60.5 13.7,58.9 13.7,56.6 14.5,55.8 15.2,55.8 v15.6,55.4
VSS  (via drill 0.7)  (1 unrouted)
  Top 0.406: EEPROM1.4 12.06,18.41 v12.7,19.05 | 9.27,5.71 EEPROM2.4 12.06,5.71 v12.7,6.35 16.38,2.92 26.67,2.92 26.67,3.81 24.77,5.71 EEPROM4.4 | EEPROM3.4 27.3,18.41 v27.94,19.05 | R17.1 42.58,25.57 42.55,25.53 42.61,25.46 42.61,25.4 | 42.61,25.4 U$2.P$4 42.6,21.41 42.55,21.46 v42.55,18.03 42.42,18.03 41.91,17.78 39.37,17.78 38.1,16.51 U$2.P$20 38.23,3.94 38.23,2.67 38.86,1.91 51.31,1.91 51.69,2.41 U$2.P$29 | 42.61,25.4 42.67,25.4 | 42.61,25.4 43.05,25.4 46.9,25.44 R16.1 47.5,25.27 47.5,26.67 v48.77,27.69 | Q4.3 59.52,29.04 58.42,27.94 C3.2 56.77,30.99 57.78,32.13 61.72,32.13 64.26,34.67 64.26,34.9 | RDIO2.7 76.2,53.34 77.47,54.61 v77.47,55.5 77.47,72.39 76.2,73.66 RDIO1.7 74.93,73.93 | 40.64,57.66 R19.1 | 40.64,57.66 39,57.62 | 39,57.62 R20.1 | 45.34,57.66 40.64,57.66 | 45.34,57.66 46.48,58.8 46.61,59.82 Q5.2 | Q5.2 46.86,59.82 C1.2 49.91,56.64 v52.58,55.12 | Q5.2 46.99,59.82 46.74,59.82 | Q3.2 52.2,58.04 52.07,58.03 | 45.34,57.66 52.07,58.03 | 52.07,58.03 52.07,58.04 58.04,58.04 Q2.2 59.69,59.69 v61.98,61.34 | D2.A v29.08,38.61 31.75,41.27 35.69,41.4 C9.2 40.89,41.53 PIC32MX320F128H.9 40.39,41.53 50.93,41.78 52.2,40.64 | 54.76,41.83 54.36,41.02 54.23,40.64 52.2,40.64 | 54.76,41.83 54.99,42.29 PIC32MX320F128H.41 56.01,42.29 57.4,42.29 58.17,41.15 58.17,39.24 59.05,38.48 61.85,38.48 64.26,36.07 64.26,34.9 | 52.2,40.64 52.2,39.5 50.8,38.1 49.53,38.1 48.64,37.08 48.64,34.16 PIC32MX320F128H.25 v48.77,30.73 | 6.99,68.45 S1.1 | S1.1 S1.2 5.08,73.66 3.81,72.39 LED1.C | S1.1 6.99,73.79 7.62,74.93 24.13,74.93 25.4,73.66 SPI2SCKT.10 | 54.76,41.83 54.61,41.91 v53.34,46.99 | 64.26,34.9 64.3,34.9 65.08,34.12 S2.1 S2.2 79.01,34.01 79,34 80,34 81,33 81,27 80,26 UART.3
  Top 0.406: C5.2 33.02,66.02 v34,67 | 39,57.62 39,57.6 v38.9,57.6 | v28.5,69.4 28.05,69.85 SPI2SCKT.9 25.4,67.4 25,67 22,67 21,66 20.9,65.5 20.3,64.8 | 20.3,64.8 ICSPHEADER.3 | v16.5,61.4 19.4,61.4 20.2,61.9 20.2,64.7 20.3,64.8 | 7,69 8.5,69 9.2,68.3 v9.2,67.5 | 74.93,73.93 75,74 | POWER.1 70.89,69.89 74.93,73.93
  Bottom 0.406: v12.7,6.35 v12.7,19.05 20.83,19.05 20.95,18.8 22.1,18.8 22.35,19.05 v27.94,19.05 41.53,19.05 v42.55,18.03 | v61.98,61.34 65.79,55.5 v77.47,55.5 | v29.08,38.61 21.59,38.61 20.32,36.83 20.32,34.4 20.3,34.4 18.92,33.02 C2.2 | v48.77,27.69 v48.77,30.73 | v53.34,46.99 v52.58,55.12 | v34,67 37,67 38,66 38,58.5 v38.9,57.6 | v34,67 34.1,66.9 | v28.5,69.4 31.6,69.4 v34,67 | v9.2,67.5 9.2,65.2 10.1,64.3 12.6,64.3 15.6,61.4 v16.5,61.4

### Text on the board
tPlace: 7 | 2 | 10 | 1 | 9 | + | - | 5 | 1 | 1 | 7 | PIC32 dev board | & bluetooth datalogger | GENIO | v1.00 | 22-May-2008 | RDIO | Ben Stabler | SPI2 | 1 | Bluetooth | SPI | C2 | 1 | 3
_tsilk: 10k | 10k | 10k | 7 | 2 | 10 | LED1 | S1 | R13 | R15 | R14 | 1 | POWER | 9 | S4 | S3 | + | - | 5 | 1 | LED4 | LED3 | LED2 | D3 | ICSPHEADER | Q5 | Q3 | Q2 | 3k | 15k | Q1 | R3 | R2 | R1 | R20 | R19 | 1 | R4 | 10k | D1 | 10k | RDIO1 | 10k | C1 | 10k | 10 uF | 7 | PIC32MX320F128H | PIC32 dev board | & bluetooth datalogger | GENIO | v1.00 | 22-May-2008 | RDIO | X1 | Ben Stabler | C9 | SPI2 | 10 uF | 1 | Bluetooth | SPI | RDIO2 | D2 | 0.1 uF | S2 | C4 | 5.1V zener | Q4 | C2 | C3 | UART | 10k | R17 | R16 | 0.1 uF | 10k | R11 | R18 | EEPROM1 | EEPROM3 | 10k | 1 | 3 | R9 | 10k | 10k | 10k | 10k | R5 | 1 | 7 | 8 | 12 | 13 | 19 | R7 | R12 | 10k | BISMS02BI-01 | R10 | EEPROM2 | EEPROM4 | 10k | 10k | R6 | 10k | R8 | 20 | 35 | 36 | 42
